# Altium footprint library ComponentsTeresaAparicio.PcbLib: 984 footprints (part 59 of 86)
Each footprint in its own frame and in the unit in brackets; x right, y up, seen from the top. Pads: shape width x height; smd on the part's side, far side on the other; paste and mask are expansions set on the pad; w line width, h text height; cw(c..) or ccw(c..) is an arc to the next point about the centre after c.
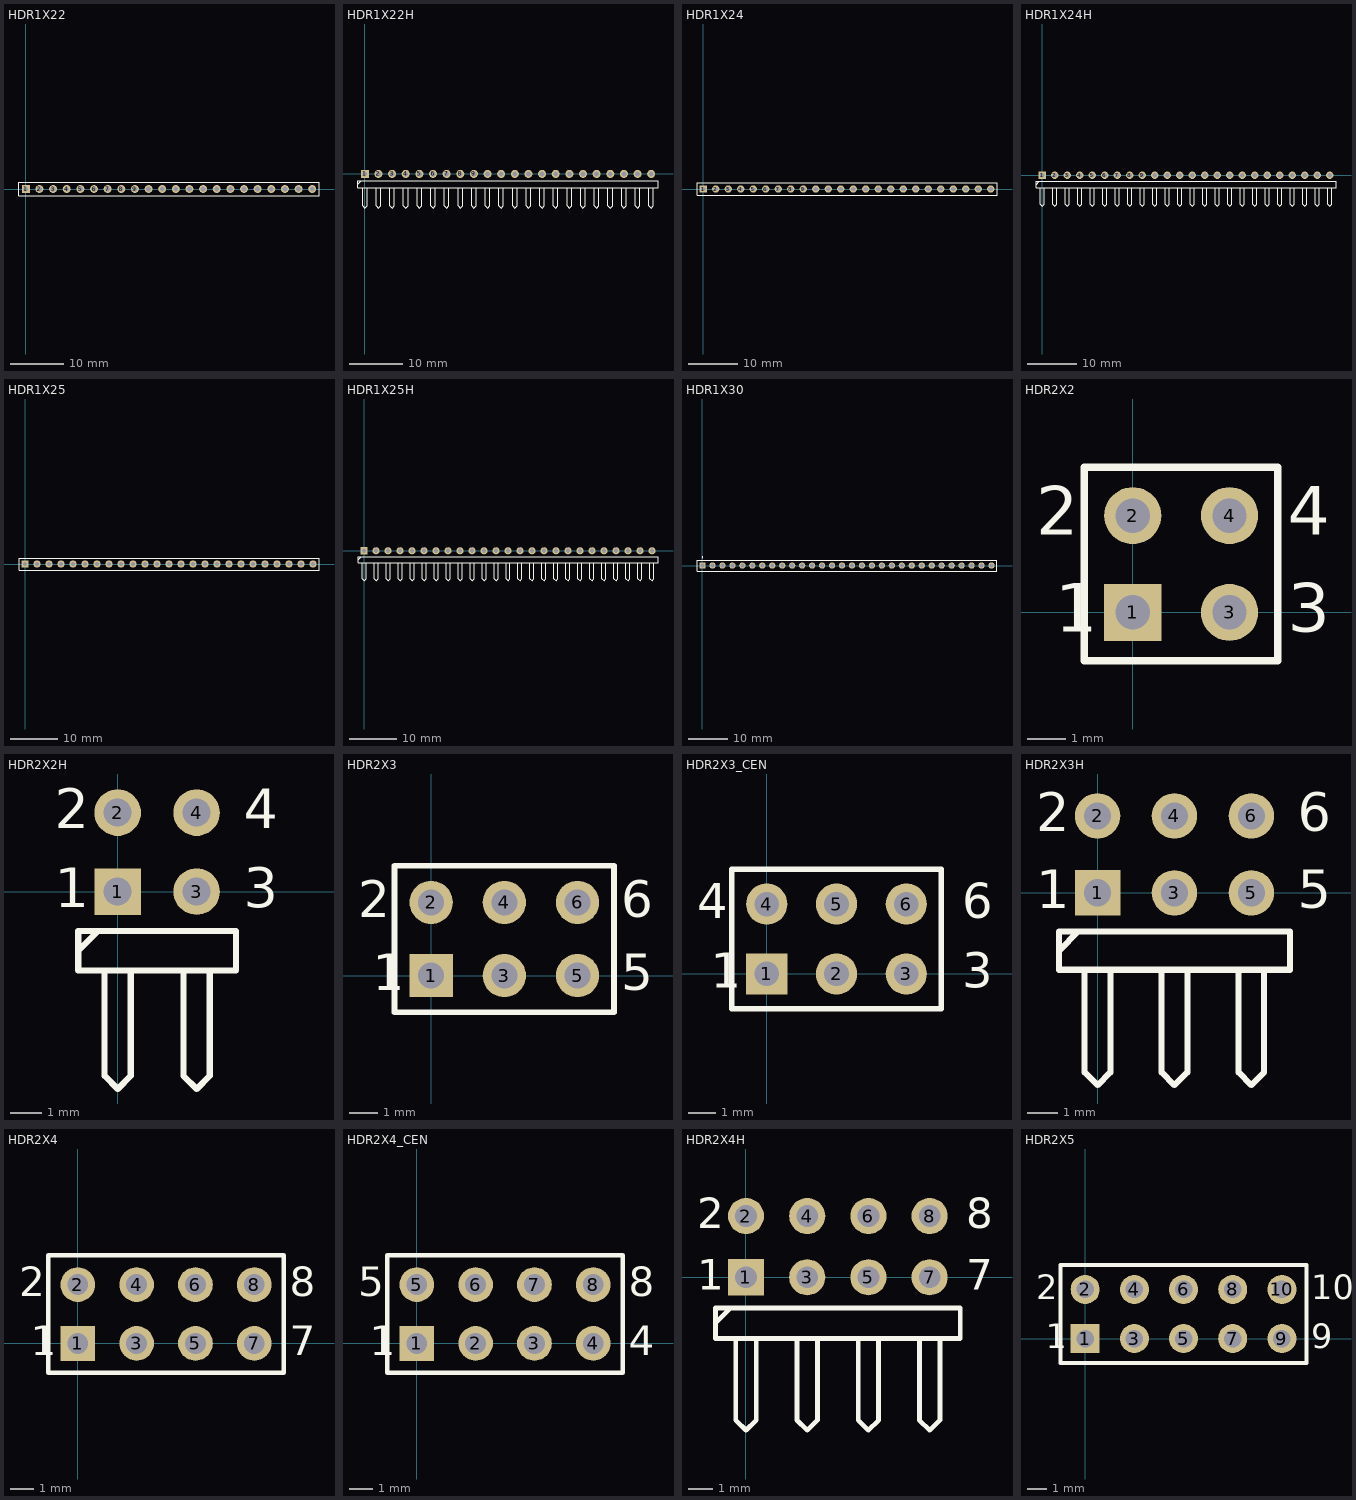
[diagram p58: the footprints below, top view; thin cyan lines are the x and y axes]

## HDR1X22 [mm] "Connector; Header; 22 Position"
pads (22):
  rect 1.5x1.5 hole 0.9: 1(0,0)
  round 1.5 hole 0.9: 2(2.54,0) 3(5.08,0) 4(7.62,0) 5(10.16,0) 6(12.7,0) 7(15.24,0) 8(17.78,0) 9(20.32,0) 10(22.86,0) 11(25.4,0) 12(27.94,0) 13(30.48,0) 14(33.02,0) 15(35.56,0) 16(38.1,0) 17(40.64,0) 18(43.18,0) 19(45.72,0) 20(48.26,0) 21(50.8,0) 22(53.34,0)
Top Overlay:
  lines w0.2: -1.27,-1.27 54.61,-1.27 54.61,1.27 0.635,1.27 -1.27,1.27 -1.27,-1.27

## HDR1X22H [mm] "Connector; Header; 22 Position; Right Angle"
pads (22):
  rect 1.5x1.5 hole 0.9: 1(0,0)
  round 1.5 hole 0.9: 2(2.54,0) 3(5.08,0) 4(7.62,0) 5(10.16,0) 6(12.7,0) 7(15.24,0) 8(17.78,0) 9(20.32,0) 10(22.86,0) 11(25.4,0) 12(27.94,0) 13(30.48,0) 14(33.02,0) 15(35.56,0) 16(38.1,0) 17(40.64,0) 18(43.18,0) 19(45.72,0) 20(48.26,0) 21(50.8,0) 22(53.34,0)
Top Overlay:
  lines w0.2: -1.27,-1.905 -0.635,-1.27 ; -0.423,-2.54 -0.423,-5.927 0,-6.35 0.423,-5.927 0.423,-2.54 ; 2.117,-2.54 2.117,-5.927 2.54,-6.35 2.963,-5.927 2.963,-2.54 ; 4.657,-2.54 4.657,-5.927 5.08,-6.35 5.503,-5.927 5.503,-2.54 ; 7.197,-2.54 7.197,-5.927 7.62,-6.35 8.043,-5.927 8.043,-2.54 ; 9.737,-2.54 9.737,-5.927 10.16,-6.35 10.583,-5.927 10.583,-2.54 ; 12.277,-2.54 12.277,-5.927 12.7,-6.35 13.123,-5.927 13.123,-2.54 ; 14.817,-2.54 14.817,-5.927 15.24,-6.35 15.663,-5.927 15.663,-2.54 ; 17.357,-2.54 17.357,-5.927 17.78,-6.35 18.203,-5.927 18.203,-2.54 ; 19.897,-2.54 19.897,-5.927 20.32,-6.35 20.743,-5.927 20.743,-2.54 ; 22.437,-2.54 22.437,-5.927 22.86,-6.35 23.283,-5.927 23.283,-2.54 ; 24.977,-2.54 24.977,-5.927 25.4,-6.35 25.823,-5.927 25.823,-2.54 ; 27.517,-2.54 27.517,-5.927 27.94,-6.35 28.363,-5.927 28.363,-2.54 ; 30.057,-2.54 30.057,-5.927 30.48,-6.35 30.903,-5.927 30.903,-2.54 ; 32.597,-2.54 32.597,-5.927 33.02,-6.35 33.443,-5.927 33.443,-2.54 ; 35.137,-2.54 35.137,-5.927 35.56,-6.35 35.983,-5.927 35.983,-2.54 ; 37.677,-2.54 37.677,-5.927 38.1,-6.35 38.523,-5.927 38.523,-2.54 ; 40.217,-2.54 40.217,-5.927 40.64,-6.35 41.063,-5.927 41.063,-2.54 ; 42.757,-2.54 42.757,-5.927 43.18,-6.35 43.603,-5.927 43.603,-2.54 ; 45.297,-2.54 45.297,-5.927 45.72,-6.35 46.143,-5.927 46.143,-2.54 ; 47.837,-2.54 47.837,-5.927 48.26,-6.35 48.683,-5.927 48.683,-2.54 ; 50.377,-2.54 50.377,-5.927 50.8,-6.35 51.223,-5.927 51.223,-2.54 ; 52.917,-2.54 52.917,-5.927 53.34,-6.35 53.763,-5.927 53.763,-2.54 ; -1.27,-2.54 -1.27,-1.27 0.635,-1.27 54.61,-1.27 54.61,-2.54 -1.27,-2.54

## HDR1X24 [mm] "Connector; Header; 24 Position"
pads (24):
  rect 1.5x1.5 hole 0.9: 1(0,0)
  round 1.5 hole 0.9: 2(2.54,0) 3(5.08,0) 4(7.62,0) 5(10.16,0) 6(12.7,0) 7(15.24,0) 8(17.78,0) 9(20.32,0) 10(22.86,0) 11(25.4,0) 12(27.94,0) 13(30.48,0) 14(33.02,0) 15(35.56,0) 16(38.1,0) 17(40.64,0) 18(43.18,0) 19(45.72,0) 20(48.26,0) 21(50.8,0) 22(53.34,0) 23(55.88,0) 24(58.42,0)
Top Overlay:
  lines w0.2: -1.27,-1.27 59.69,-1.27 59.69,1.27 0.635,1.27 -1.27,1.27 -1.27,-1.27

## HDR1X24H [mm] "Connector; Header; 24 Position; Right Angle"
pads (24):
  rect 1.5x1.5 hole 0.9: 1(0,0)
  round 1.5 hole 0.9: 2(2.54,0) 3(5.08,0) 4(7.62,0) 5(10.16,0) 6(12.7,0) 7(15.24,0) 8(17.78,0) 9(20.32,0) 10(22.86,0) 11(25.4,0) 12(27.94,0) 13(30.48,0) 14(33.02,0) 15(35.56,0) 16(38.1,0) 17(40.64,0) 18(43.18,0) 19(45.72,0) 20(48.26,0) 21(50.8,0) 22(53.34,0) 23(55.88,0) 24(58.42,0)
Top Overlay:
  lines w0.2: -1.27,-1.905 -0.635,-1.27 ; -0.423,-2.54 -0.423,-5.927 0,-6.35 0.423,-5.927 0.423,-2.54 ; 2.117,-2.54 2.117,-5.927 2.54,-6.35 2.963,-5.927 2.963,-2.54 ; 4.657,-2.54 4.657,-5.927 5.08,-6.35 5.503,-5.927 5.503,-2.54 ; 7.197,-2.54 7.197,-5.927 7.62,-6.35 8.043,-5.927 8.043,-2.54 ; 9.737,-2.54 9.737,-5.927 10.16,-6.35 10.583,-5.927 10.583,-2.54 ; 12.277,-2.54 12.277,-5.927 12.7,-6.35 13.123,-5.927 13.123,-2.54 ; 14.817,-2.54 14.817,-5.927 15.24,-6.35 15.663,-5.927 15.663,-2.54 ; 17.357,-2.54 17.357,-5.927 17.78,-6.35 18.203,-5.927 18.203,-2.54 ; 19.897,-2.54 19.897,-5.927 20.32,-6.35 20.743,-5.927 20.743,-2.54 ; 22.437,-2.54 22.437,-5.927 22.86,-6.35 23.283,-5.927 23.283,-2.54 ; 24.977,-2.54 24.977,-5.927 25.4,-6.35 25.823,-5.927 25.823,-2.54 ; 27.517,-2.54 27.517,-5.927 27.94,-6.35 28.363,-5.927 28.363,-2.54 ; 30.057,-2.54 30.057,-5.927 30.48,-6.35 30.903,-5.927 30.903,-2.54 ; 32.597,-2.54 32.597,-5.927 33.02,-6.35 33.443,-5.927 33.443,-2.54 ; 35.137,-2.54 35.137,-5.927 35.56,-6.35 35.983,-5.927 35.983,-2.54 ; 37.677,-2.54 37.677,-5.927 38.1,-6.35 38.523,-5.927 38.523,-2.54 ; 40.217,-2.54 40.217,-5.927 40.64,-6.35 41.063,-5.927 41.063,-2.54 ; 42.757,-2.54 42.757,-5.927 43.18,-6.35 43.603,-5.927 43.603,-2.54 ; 45.297,-2.54 45.297,-5.927 45.72,-6.35 46.143,-5.927 46.143,-2.54 ; 47.837,-2.54 47.837,-5.927 48.26,-6.35 48.683,-5.927 48.683,-2.54 ; 50.377,-2.54 50.377,-5.927 50.8,-6.35 51.223,-5.927 51.223,-2.54 ; 52.917,-2.54 52.917,-5.927 53.34,-6.35 53.763,-5.927 53.763,-2.54 ; 55.457,-2.54 55.457,-5.927 55.88,-6.35 56.303,-5.927 56.303,-2.54 ; 57.997,-2.54 57.997,-5.927 58.42,-6.35 58.843,-5.927 58.843,-2.54 ; -1.27,-2.54 59.69,-2.54 59.69,-1.27 0.635,-1.27 -1.27,-1.27 -1.27,-2.54

## HDR1X25 [mm] "Connector; Header; 25 Position"
pads (25):
  rect 1.5x1.5 hole 0.9: 1(0,0)
  round 1.5 hole 0.9: 2(2.54,0) 3(5.08,0) 4(7.62,0) 5(10.16,0) 6(12.7,0) 7(15.24,0) 8(17.78,0) 9(20.32,0) 10(22.86,0) 11(25.4,0) 12(27.94,0) 13(30.48,0) 14(33.02,0) 15(35.56,0) 16(38.1,0) 17(40.64,0) 18(43.18,0) 19(45.72,0) 20(48.26,0) 21(50.8,0) 22(53.34,0) 23(55.88,0) 24(58.42,0) 25(60.96,0)
Top Overlay:
  lines w0.2: -1.27,-1.27 -1.27,1.27 0.635,1.27 62.23,1.27 62.23,-1.27 -1.27,-1.27

## HDR1X25H [mm] "Connector; Header; 25 Position; Right Angle"
pads (25):
  rect 1.5x1.5 hole 0.9: 1(0,0)
  round 1.5 hole 0.9: 2(2.54,0) 3(5.08,0) 4(7.62,0) 5(10.16,0) 6(12.7,0) 7(15.24,0) 8(17.78,0) 9(20.32,0) 10(22.86,0) 11(25.4,0) 12(27.94,0) 13(30.48,0) 14(33.02,0) 15(35.56,0) 16(38.1,0) 17(40.64,0) 18(43.18,0) 19(45.72,0) 20(48.26,0) 21(50.8,0) 22(53.34,0) 23(55.88,0) 24(58.42,0) 25(60.96,0)
Top Overlay:
  lines w0.2: -1.27,-1.905 -0.635,-1.27 ; -0.423,-2.54 -0.423,-5.927 0,-6.35 0.423,-5.927 0.423,-2.54 ; 2.117,-2.54 2.117,-5.927 2.54,-6.35 2.963,-5.927 2.963,-2.54 ; 4.657,-2.54 4.657,-5.927 5.08,-6.35 5.503,-5.927 5.503,-2.54 ; 7.197,-2.54 7.197,-5.927 7.62,-6.35 8.043,-5.927 8.043,-2.54 ; 9.737,-2.54 9.737,-5.927 10.16,-6.35 10.583,-5.927 10.583,-2.54 ; 12.277,-2.54 12.277,-5.927 12.7,-6.35 13.123,-5.927 13.123,-2.54 ; 14.817,-2.54 14.817,-5.927 15.24,-6.35 15.663,-5.927 15.663,-2.54 ; 17.357,-2.54 17.357,-5.927 17.78,-6.35 18.203,-5.927 18.203,-2.54 ; 19.897,-2.54 19.897,-5.927 20.32,-6.35 20.743,-5.927 20.743,-2.54 ; 22.437,-2.54 22.437,-5.927 22.86,-6.35 23.283,-5.927 23.283,-2.54 ; 24.977,-2.54 24.977,-5.927 25.4,-6.35 25.823,-5.927 25.823,-2.54 ; 27.517,-2.54 27.517,-5.927 27.94,-6.35 28.363,-5.927 28.363,-2.54 ; 30.057,-2.54 30.057,-5.927 30.48,-6.35 30.903,-5.927 30.903,-2.54 ; 32.597,-2.54 32.597,-5.927 33.02,-6.35 33.443,-5.927 33.443,-2.54 ; 35.137,-2.54 35.137,-5.927 35.56,-6.35 35.983,-5.927 35.983,-2.54 ; 37.677,-2.54 37.677,-5.927 38.1,-6.35 38.523,-5.927 38.523,-2.54 ; 40.217,-2.54 40.217,-5.927 40.64,-6.35 41.063,-5.927 41.063,-2.54 ; 42.757,-2.54 42.757,-5.927 43.18,-6.35 43.603,-5.927 43.603,-2.54 ; 45.297,-2.54 45.297,-5.927 45.72,-6.35 46.143,-5.927 46.143,-2.54 ; 47.837,-2.54 47.837,-5.927 48.26,-6.35 48.683,-5.927 48.683,-2.54 ; 50.377,-2.54 50.377,-5.927 50.8,-6.35 51.223,-5.927 51.223,-2.54 ; 52.917,-2.54 52.917,-5.927 53.34,-6.35 53.763,-5.927 53.763,-2.54 ; 55.457,-2.54 55.457,-5.927 55.88,-6.35 56.303,-5.927 56.303,-2.54 ; 57.997,-2.54 57.997,-5.927 58.42,-6.35 58.843,-5.927 58.843,-2.54 ; 60.537,-2.54 60.537,-5.927 60.96,-6.35 61.383,-5.927 61.383,-2.54 ; -1.27,-2.54 -1.27,-1.27 0.635,-1.27 62.23,-1.27 62.23,-2.54 -1.27,-2.54

## HDR1X30 [mm] "Connector; Header; 30 Position"
pads (30):
  rect 1.6x1.6 hole 0.99: 1(0,0)
  round 1.6 hole 0.99: 2(2.54,0) 3(5.08,0) 4(7.62,0) 5(10.16,0) 6(12.7,0) 7(15.24,0) 8(17.78,0) 9(20.32,0) 10(22.86,0) 11(25.4,0) 12(27.94,0) 13(30.48,0) 14(33.02,0) 15(35.56,0) 16(38.1,0) 17(40.64,0) 18(43.18,0) 19(45.72,0) 20(48.26,0) 21(50.8,0) 22(53.34,0) 23(55.88,0) 24(58.42,0) 25(60.96,0) 26(63.5,0) 27(66.04,0) 28(68.58,0) 29(71.12,0) 30(73.66,0)
Top Overlay:
  circle w0.25: c0,2.05 r0.125
  lines w0.2: -1.4,-1.4 -1.4,1.4 75.06,1.4 75.06,-1.4 -1.4,-1.4

## HDR2X2 [mm] "Connector; Header; 2x2 Position"
pads (4):
  rect 1.5x1.5 hole 0.9: 1(0,0)
  round 1.5 hole 0.9: 2(0,2.54) 3(2.54,0) 4(2.54,2.54)
Top Overlay:
  lines w0.2: -1.27,-1.27 3.81,-1.27 3.81,3.81 -1.27,3.81 -1.27,-1.27
  text "3" at 4.064,-0.508 h1.27
  text "4" at 4.064,2.032 h1.27
  text "2" at -2.54,2.032 h1.27
  text "1" at -2.032,-0.508 h1.27

## HDR2X2H [mm] "Connector; Header; 2x2 Position; Right Angle"
pads (4):
  rect 1.5x1.5 hole 0.9: 1(0,0)
  round 1.5 hole 0.9: 2(0,2.54) 3(2.54,0) 4(2.54,2.54)
Top Overlay:
  lines w0.2: -1.27,-1.905 -0.635,-1.27 ; -0.423,-2.54 -0.423,-5.927 0,-6.35 0.423,-5.927 0.423,-2.54 ; 2.117,-2.54 2.117,-5.927 2.54,-6.35 2.963,-5.927 2.963,-2.54 ; -1.27,-2.54 3.81,-2.54 3.81,-1.27 -1.27,-1.27 -1.27,-2.54
  text "3" at 4.064,-0.508 h1.27
  text "4" at 4.064,2.032 h1.27
  text "2" at -2.032,2.032 h1.27
  text "1" at -2.032,-0.508 h1.27

## HDR2X3 [mm] "Connector; Header; 3x2 Position"
pads (6):
  rect 1.5x1.5 hole 0.9: 1(0,0)
  round 1.5 hole 0.9: 2(0,2.54) 3(2.54,0) 4(2.54,2.54) 5(5.08,0) 6(5.08,2.54)
Top Overlay:
  lines w0.2: 1.482,-1.27 6.35,-1.27 ; 6.35,-1.27 -1.27,-1.27 -1.27,3.81 6.35,3.81 6.35,-1.27
  text "1" at -2.032,-0.508 h1.27
  text "2" at -2.54,2.032 h1.27
  text "5" at 6.604,-0.508 h1.27
  text "6" at 6.604,2.032 h1.27

## HDR2X3_CEN [mm] "Connector; Header; 3x2 Position"
pads (6):
  rect 1.5x1.5 hole 0.9: 1(0,0)
  round 1.5 hole 0.9: 2(2.54,0) 3(5.08,0) 4(0,2.54) 5(2.54,2.54) 6(5.08,2.54)
Top Overlay:
  lines w0.2: -1.27,-1.27 6.35,-1.27 6.35,3.81 -1.27,3.81 -1.27,-1.27
  text "6" at 7.112,2.032 h1.27
  text "3" at 7.112,-0.508 h1.27
  text "1" at -2.032,-0.508 h1.27
  text "4" at -2.54,2.032 h1.27

## HDR2X3H [mm] "Connector; Header; 3x2 Position; Right Angle"
pads (6):
  rect 1.5x1.5 hole 0.9: 1(0,0)
  round 1.5 hole 0.9: 2(0,2.54) 3(2.54,0) 4(2.54,2.54) 5(5.08,0) 6(5.08,2.54)
Top Overlay:
  lines w0.2: -1.27,-1.905 -0.635,-1.27 ; -0.423,-2.54 -0.423,-5.927 0,-6.35 0.423,-5.927 0.423,-2.54 ; 2.117,-2.54 2.117,-5.927 2.54,-6.35 2.963,-5.927 2.963,-2.54 ; 4.657,-2.54 4.657,-5.927 5.08,-6.35 5.503,-5.927 5.503,-2.54 ; -1.27,-2.54 -1.27,-1.27 6.35,-1.27 6.35,-2.54 -1.27,-2.54
  text "6" at 6.604,2.032 h1.27
  text "5" at 6.604,-0.508 h1.27
  text "1" at -2.032,-0.508 h1.27
  text "2" at -2.032,2.032 h1.27

## HDR2X4 [mm] "Connector; Header; 4x2 Position"
pads (8):
  rect 1.5x1.5 hole 0.9: 1(0,0)
  round 1.5 hole 0.9: 2(0,2.54) 3(2.54,0) 4(2.54,2.54) 5(5.08,0) 6(5.08,2.54) 7(7.62,0) 8(7.62,2.54)
Top Overlay:
  lines w0.2: -1.27,-1.27 -1.27,3.81 8.89,3.81 8.89,-1.27 -1.27,-1.27
  text "8" at 9.144,2.032 h1.27
  text "7" at 9.144,-0.508 h1.27
  text "1" at -2.032,-0.508 h1.27
  text "2" at -2.54,2.032 h1.27

## HDR2X4_CEN [mm] "Connector; Header; 4x2 Position"
pads (8):
  rect 1.5x1.5 hole 0.9: 1(0,0)
  round 1.5 hole 0.9: 2(2.54,0) 3(5.08,0) 4(7.62,0) 5(0,2.54) 6(2.54,2.54) 7(5.08,2.54) 8(7.62,2.54)
Top Overlay:
  lines w0.2: -1.27,-1.27 -1.27,3.81 8.89,3.81 8.89,-1.27 -1.27,-1.27
  text "8" at 9.144,2.032 h1.27
  text "4" at 9.144,-0.508 h1.27
  text "1" at -2.032,-0.508 h1.27
  text "5" at -2.54,2.032 h1.27

## HDR2X4H [mm] "Connector; Header; 4x2 Position; Right Angle"
pads (8):
  rect 1.5x1.5 hole 0.9: 1(0,0)
  round 1.5 hole 0.9: 2(0,2.54) 3(2.54,0) 4(2.54,2.54) 5(5.08,0) 6(5.08,2.54) 7(7.62,0) 8(7.62,2.54)
Top Overlay:
  lines w0.2: -1.27,-1.905 -0.635,-1.27 ; -0.423,-2.54 -0.423,-5.927 0,-6.35 0.423,-5.927 0.423,-2.54 ; 2.117,-2.54 2.117,-5.927 2.54,-6.35 2.963,-5.927 2.963,-2.54 ; 4.657,-2.54 4.657,-5.927 5.08,-6.35 5.503,-5.927 5.503,-2.54 ; 7.197,-2.54 7.197,-5.927 7.62,-6.35 8.043,-5.927 8.043,-2.54 ; -1.27,-2.54 8.89,-2.54 8.89,-1.27 -1.27,-1.27 -1.27,-2.54
  text "2" at -2.032,2.032 h1.27
  text "1" at -2.032,-0.508 h1.27
  text "7" at 9.144,-0.508 h1.27
  text "8" at 9.144,2.032 h1.27

## HDR2X5 [mm] "Connector; Header; 5x2 Position"
pads (10):
  rect 1.5x1.5 hole 0.9: 1(0,0)
  round 1.5 hole 0.9: 2(0,2.54) 3(2.54,0) 4(2.54,2.54) 5(5.08,0) 6(5.08,2.54) 7(7.62,0) 8(7.62,2.54) 9(10.16,0) 10(10.16,2.54)
Top Overlay:
  lines w0.2: -1.27,-1.27 -1.27,3.81 11.43,3.81 11.43,-1.27 -1.27,-1.27
  text "2" at -2.54,2.032 h1.27
  text "1" at -2.032,-0.508 h1.27
  text "9" at 11.684,-0.508 h1.27
  text "10" at 11.684,2.032 h1.27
